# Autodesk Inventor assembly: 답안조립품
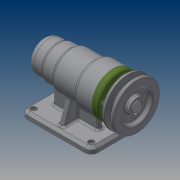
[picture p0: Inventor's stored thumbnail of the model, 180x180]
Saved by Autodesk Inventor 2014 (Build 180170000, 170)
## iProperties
Created: 2016-06
Part Number: 답안조립품
Document SubType Name: Assembly
Designer: SEC
Author: SEC
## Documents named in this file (12)
- C:\Documents and Settings\SEC\바탕 화면\460607V1005\답안조립품.iam
- C:\Documents and Settings\SEC\바탕 화면\460607V1005\1-본체.ipt
- C:\Documents and Settings\SEC\바탕 화면\460607V1005\커버.ipt
- C:\Documents and Settings\SEC\바탕 화면\460607V1005\베어링 6004.ipt
- C:\Documents and Settings\SEC\바탕 화면\460607V1005\축.ipt
- C:\Documents and Settings\SEC\바탕 화면\460607V1005\어댑터슬리브.ipt
- C:\Documents and Settings\SEC\바탕 화면\460607V1005\볼트 M4 x 12.ipt
- C:\Documents and Settings\SEC\바탕 화면\460607V1005\베어링 51202.ipt
- C:\Documents and Settings\SEC\바탕 화면\460607V1005\키 5 x 5 x 16.ipt
- C:\Documents and Settings\SEC\바탕 화면\460607V1005\V벨트풀리.ipt
- C:\Documents and Settings\SEC\바탕 화면\460607V1005\멈춤나사 M3x8.ipt
- C:\Documents and Settings\SEC\바탕 화면\460607V1005\오일 실.ipt
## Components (7 placed, 3 different names)
1. 1-본체:1
2. ISO 4762 M4 x 12:1
3. V벨트풀리:1 — 각도:2
4. ISO 4762 M4 x 12:2
5. ISO 4762 M4 x 12:3
6. ISO 4762 M4 x 12:4
7. ISO 4762 M4 x 12:5
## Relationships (1: Angle 1)
- 각도:2 [Angle]: V벨트풀리:1
